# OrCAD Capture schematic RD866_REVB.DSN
size Custom; title: DER 866; rev: A
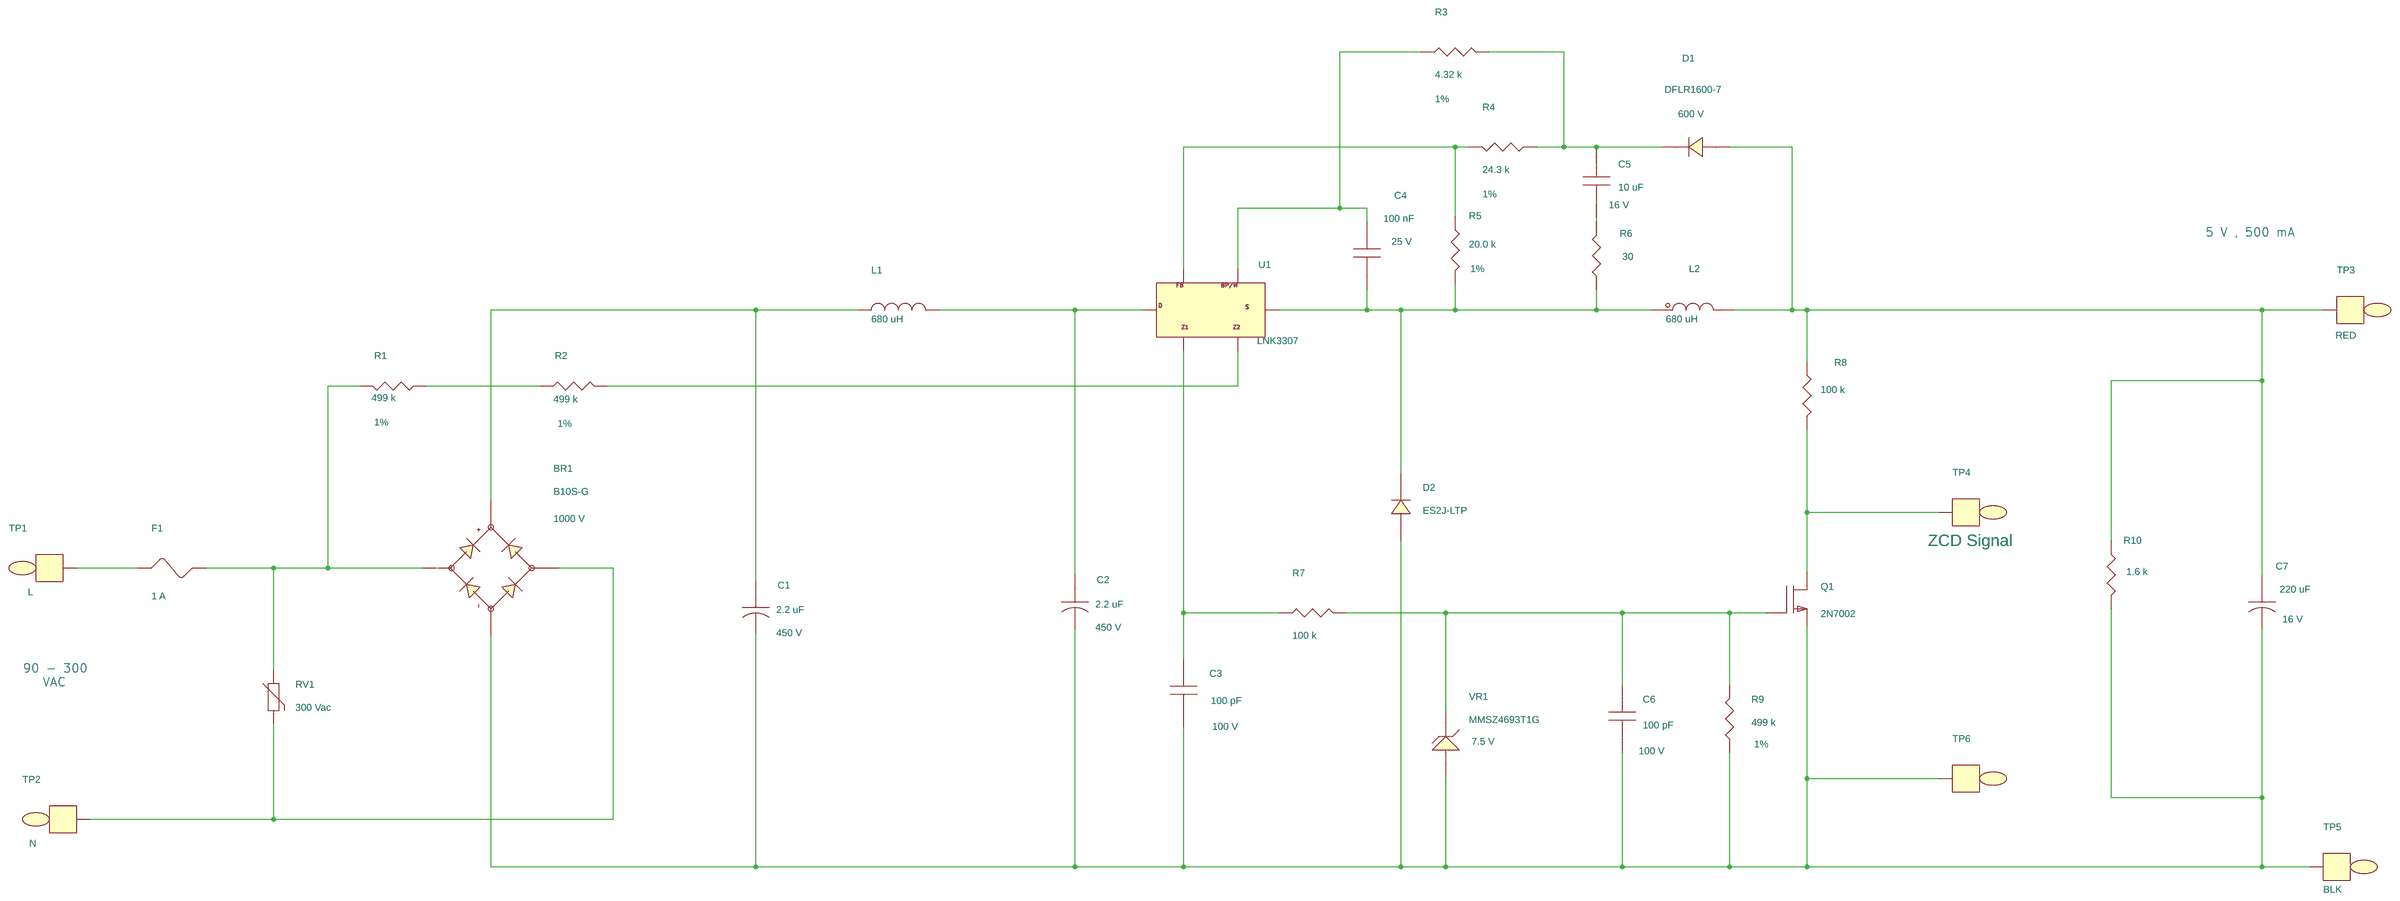
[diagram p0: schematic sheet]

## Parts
BR1  B10S-G  [pismsoic4]
C1  2.2 uF  [pipolcapclyd320ls140030430h]
C2  2.2 uF  [pipolcapclyd320ls140030430h]
C3  100 pF  [pismc0805]
C4  100 nF  [pismc0805]
C5  10 uF  [pismc0805]
C6  100 pF  [pismc0805]
C7  220 uF  [pipolcapclyd6p3x9mm_h]
D1  DFLR1600-7  [pismddflr120012]
D2  ES2J-LTP  [pismdo214ac12]
F1  1 A  [pi_rst_microfuse]
L1  680 uH  [pichoketokinvd216h413ls098d030]
L2  680 uH  [pi_choke_RL5480-4_d2]
Q1  2N7002  [pismsot23123_1]
R1  499 k  [pismr0805]
R2  499 k  [pismr0805]
R3  4.32 k  [pismr0805]
R4  24.3 k  [pismr0805]
R5  20.0 k  [pismr0805]
R6  30  [pismr0805]
R7  100 k  [pismr0805]
R8  100 k  [pismr0805]
R9  499 k  [pismr0805]
R10  1.6 k  [pismr0805]
RV1  300 Vac  [pidisc350x225ls240x140040]
TP1  L  [pitpkeystone100x100]
TP2  N  [pitpkeystone100x100]
TP3  RED  [pitpkeystone100x100]
TP4  ZCD Signal  [pitpkeystone100x100]
TP5  BLK  [pitpkeystone100x100]
TP6  BLK  [pitpkeystone100x100]
U1  LNK3307  [pismso8_nop3]
VR1  MMSZ4693T1G  [pi_sm_sod-123_12]

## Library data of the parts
BR1 = DIODE_BRIDGE_~~+-: ALT_SYMBOLS: pi_sm_soic4_slot; Disp_Voltage: 1000 V; FPLIST: pismsoic4,pi_sm_soic4_slot; Part Number: 15-00818-00
C1 C2 = CAP_POL: Disp_Voltage: 450 V; FPLIST: pipolcapclyd320ls140030,pipolcapclyd320ls140030430h; Part Number: 20-08936-00; Voltage: 450 V
C3 C6 = CAP_NP: Disp_Voltage: 100 V; Part Number: 20-00581-00; Voltage: 100 V
C4 = CAP_NP: Disp_Voltage: 25 V; Part Number: 20-08599-00; Voltage: 25 V
C5 = CAP_NP: Disp_Voltage: 16 V; Part Number: 20-08964-00; Voltage: 16 V
C7 = CAP_POL: Disp_Voltage: 16 V; FPLIST: pipolcapclyd248ls098028,pipolcapclyd6p3x9mm_h; Part Number: 20-09088-00; Voltage: 16V
D1 = DIODE: Disp_Voltage: 600 V; Part Number: 15-00826-00
D2 = DIODE: Part Number: 15-01076-00
F1 = FUSE: ALT_SYMBOLS: pirstmicrofusehoz; FPLIST: pi_rst_microfuse,pirstmicrofusehoz; Part Number: 40-00053-00
L1 = INDUCTOR: Part Number: 30-00019-00
L2 = INDUCTOR_dot2: ALT_SYMBOLS: pi_choke_RL5480-4H_d2; FPLIST: pi_choke_RL5480-4_d2,pi_choke_RL5480-4H_d2; Part Number: 30-00336-00
Q1 = FET_N_GSD: Part Number: 50-00103-00
R1 R2 = R: Disp_Tol: 1%; Part Number: 05-00847-00; ROOM: 1
R3 = R: Disp_Tol: 1%; Part Number: 05-03368-00
R4 = R: Disp_Tol: 1%; Part Number: 05-00721-00
R5 = R: Disp_Tol: 1%; Part Number: 05-00713-00; Tol: 1%
R6 = R: Part Number: 05-01482-00
R7 R8 = R: Part Number: 05-01567-00
R9 = R: Disp_Tol: 1%; Part Number: 05-00847-00
R10 = R: Part Number: 05-01524-00; Tol: 1%
RV1 = VARISTOR: Part Number: 85-00031-00
TP1 TP5 TP6 = TESTPOINT: Part Number: 35-00079-00
TP2 = TESTPOINT: Part Number: 35-00081-00
TP3 = TESTPOINT: Part Number: 35-00080-00; ROOM: 2
TP4 = TESTPOINT: Part Number: 35-00397-00
U1 = LNK-TNZ: Part Number: 10-01237-00
VR1 = DIODE_ZENER: Disp_Voltage: 7.5 V; Part Number: 15-01578-00

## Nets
N361822: BR1.1 RV1.2 TP2.1
N361834: BR1.4 C1.2 C2.2 C3.2 C6.2 C7.2 D2.2 Q1.2(S) R9.1 R10.2 TP5.1 TP6.1 VR1.2
N595771: BR1.2 F1.2 R1.2 RV1.1
N596154: F1.1 TP1.1
N596955: C4.1 R3.1 U1.7
N596963: C5.1 D1.1 R3.2 R4.1
N597007: R4.2 R5.1 U1.8
N597039: C7.1 D1.2 L2.1 R8.1 R10.1 TP3.1
N597129: C4.2 D2.1 L2.2 R5.2 R6.2 U1.5
N597183: C2.1 L1.2 U1.4
N605807: R2.1 U1.2
N608013: R1.1 R2.2
N610414: BR1.3 C1.1 L1.1
N4290608: Q1.3(D) R8.2 TP4.1
N4294463: C3.1 R7.1 U1.1
N4294503: C6.1 Q1.1(G) R7.2 R9.2 VR1.1
N4315295: C5.2 R6.1

Not connected (* = marked no-connect by the designer): U1 6

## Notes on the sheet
- 5 V , 500 mA
- 90 - 300
     VAC
